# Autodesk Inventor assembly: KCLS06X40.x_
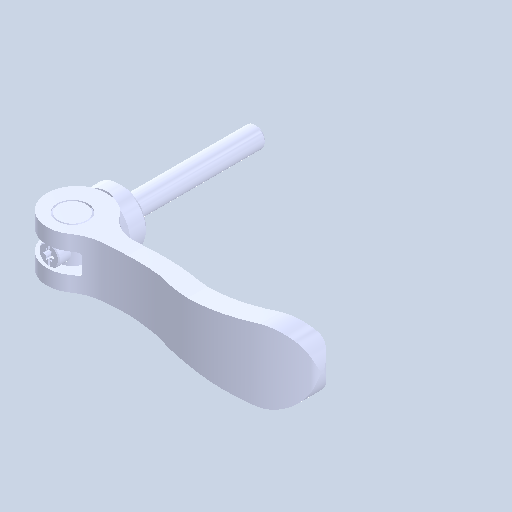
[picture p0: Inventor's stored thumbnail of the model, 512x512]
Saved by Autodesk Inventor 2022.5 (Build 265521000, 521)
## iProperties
Created: 2024-08
Part Number: KCLS06X40.x_
Document SubType Name: Assembly
Designer: ImaoCorp
Author: ImaoCorp
Sending System: SOLIDWORKS 2022-2022290
MC: AMD64
MC_MODEL: Intel64 Family 6 Model 60 Stepping 3, GenuineIntel
OS: Windows_NT
FRU: Parasolid Version 33.1, build 260,  4-25-2022
FORMAT: text
GUISE: transmit
KEY: FILEKCLS06X40.x_t
DATE: Thu Aug 29 10:54:57 2024
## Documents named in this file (5)
- Y:\5.更新分\2024年対応\1001_KCL\データ\kcls06x40\KCLS06X40.x_.iam
- Y:\5.更新分\2024年対応\1001_KCL\データ\kcls06x40\KCLS06X40_01.ipt
- Y:\5.更新分\2024年対応\1001_KCL\データ\kcls06x40\KCLS06X40_02.ipt
- Y:\5.更新分\2024年対応\1001_KCL\データ\kcls06x40\KCLS06X40_03.ipt
- Y:\5.更新分\2024年対応\1001_KCL\データ\kcls06x40\KCLS06X40_04.ipt
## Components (4 placed, 4 different names)
1. KCLS06X40_01
2. KCLS06X40_02
3. KCLS06X40_03
4. KCLS06X40_04
